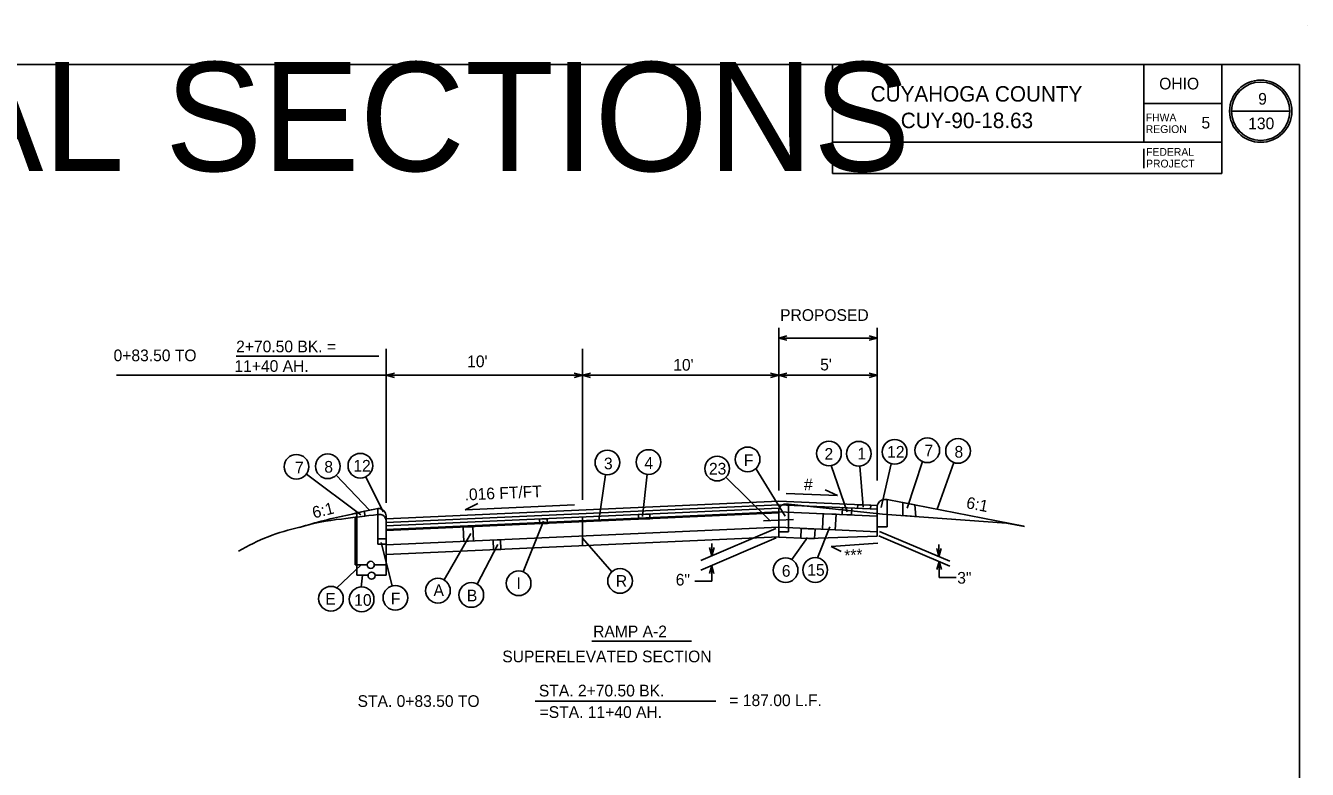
# Model space of a CAD drawing. Extents: x -210 to 558, y -150 to 205.
# Drawn here: x 491.9 to 557.8, y -100.6 to -62.3 of the extents above; entities that cross this region are included whole.
import ezdxf

# ---------------------------------------------------------------- set-up
doc = ezdxf.new("R2010")
doc.units = 0
for name, color, linetype in [('Level 1', 7, 'Continuous'), ('Level 2', 7, 'Continuous'), ('Level 4', 7, 'Continuous'), ('Level 6', 7, 'Continuous'), ('Level 60', 7, 'Continuous'), ('Level 7', 7, 'Continuous')]:
    doc.layers.add(name, color=color, linetype=linetype)

msp = doc.modelspace()

# ---------------------------------------------------------------- linework, layer by layer
at = {"layer": 'Level 1'}
for p, q in [((557.752, -62.346), (557.752, -62.346)), ((557.356, -64.342), (423.408, -64.342)), ((557.356, -148.31), (557.356, -64.342))]:
    msp.add_line(p, q, dxfattribs=at)
at = {"layer": 'Level 2'}
for p, q in [((533.364, -64.342), (533.364, -66.342)), ((549.356, -64.342), (549.356, -66.342)), ((553.356, -64.342), (553.356, -66.342)), ((533.364, -66.342), (533.364, -68.342)), ((549.356, -66.342), (549.356, -68.342)), ((549.356, -66.342), (553.356, -66.342)), ((553.356, -66.342), (553.356, -68.342)), ((556.856, -66.742), (553.856, -66.742)), ((533.364, -68.342), (533.364, -69.942)), ((533.364, -68.342), (553.356, -68.342)), ((553.356, -68.342), (553.356, -69.942)), ((549.356, -68.674), (549.356, -69.674)), ((533.364, -69.942), (553.356, -69.942))]:
    msp.add_line(p, q, dxfattribs=at)
for radius in [1.599, 1.499]:
    msp.add_circle((555.356, -66.743), radius, dxfattribs=at)
at = {"layer": 'Level 4'}
for p, q in [((530.608, -86.23), (530.608, -77.879)), ((535.67, -85.715), (535.67, -77.879)), ((510.451, -86.855), (510.451, -78.954)), ((520.53, -78.954), (520.53, -86.704)), ((530.608, -78.397), (535.67, -78.397)), ((502.745, -79.325), (510.076, -79.325)), ((510.451, -80.312), (496.606, -80.312)), ((510.451, -80.312), (520.53, -80.312)), ((520.53, -80.312), (530.608, -80.312)), ((530.608, -80.312), (535.67, -80.312)), ((535.67, -85.715), (535.67, -82.128)), ((536.388, -84.855), (535.873, -87.099)), ((537.993, -84.748), (537.204, -87.137)), ((539.602, -84.795), (538.751, -87.196)), ((506.351, -85.39), (509.143, -87.482)), ((507.888, -85.443), (509.587, -87.233)), ((509.405, -85.526), (510.293, -87.325)), ((521.717, -85.419), (521.372, -87.775)), ((523.851, -85.397), (523.605, -87.561)), ((530.149, -87.776), (527.895, -85.551)), ((529.439, -85.097), (530.935, -87.548)), ((533.3, -84.952), (534.121, -87.318)), ((534.77, -84.972), (534.939, -87.067)), ((533.622, -86.495), (532.99, -86.191)), ((530.99, -86.377), (533.622, -86.495)), ((514.498, -87.22), (515.163, -86.9)), ((520.123, -86.968), (514.498, -87.22)), ((517.488, -90.408), (518.529, -87.808)), ((530.451, -88.187), (526.615, -89.819)), ((533.227, -88.095), (532.59, -89.689)), ((513.425, -90.826), (514.803, -88.436)), ((522.042, -90.4), (520.53, -88.682)), ((530.482, -88.67), (526.615, -90.316)), ((532.078, -88.638), (531.287, -89.782)), ((535.754, -88.562), (539.398, -90.113)), ((535.784, -88.333), (539.388, -89.867)), ((510.766, -91.128), (510.189, -88.894)), ((515.116, -91.037), (516.189, -88.998)), ((527.169, -89.583), (527.169, -88.954)), ((533.301, -89.101), (535.695, -88.931)), ((533.301, -89.101), (533.815, -89.366)), ((538.834, -89.631), (538.834, -89.002)), ((509.173, -90.05), (507.918, -91.233)), ((527.169, -90.895), (527.169, -90.08)), ((538.844, -90.692), (538.844, -89.877)), ((509.233, -90.576), (509.158, -91.188)), ((539.72, -90.692), (538.844, -90.692)), ((526.293, -90.895), (527.169, -90.895)), ((521.018, -93.977), (526.126, -93.977)), ((518.101, -97.048), (527.371, -97.048))]:
    msp.add_line(p, q, dxfattribs=at)
for points in [[(531.028, -78.513), (530.608, -78.397), (531.028, -78.285)], [(535.25, -78.281), (535.67, -78.397), (535.25, -78.509)], [(510.871, -80.428), (510.451, -80.312), (510.871, -80.2)], [(520.11, -80.196), (520.53, -80.312), (520.11, -80.424)], [(520.95, -80.428), (520.53, -80.312), (520.95, -80.2)], [(530.188, -80.196), (530.608, -80.312), (530.188, -80.424)], [(531.028, -80.428), (530.608, -80.312), (531.028, -80.2)], [(535.25, -80.196), (535.67, -80.312), (535.25, -80.424)], [(527.285, -89.163), (527.169, -89.583), (527.057, -89.163)], [(538.718, -89.211), (538.834, -89.631), (538.946, -89.211)], [(527.053, -90.5), (527.169, -90.08), (527.281, -90.5)], [(538.96, -90.297), (538.844, -89.877), (538.732, -90.297)]]:
    msp.add_lwpolyline(points, dxfattribs=at)
for centre in [(538.234, -84.162), (539.814, -84.197), (521.809, -84.791), (523.923, -84.767), (529.01, -84.631), (533.187, -84.328), (534.719, -84.34), (536.56, -84.245), (505.843, -85.01), (507.451, -84.984), (509.125, -84.957), (527.446, -85.104), (530.96, -90.326), (532.48, -90.314), (513.108, -91.376), (517.252, -90.996), (522.461, -90.876), (507.616, -91.79), (509.191, -91.821), (510.925, -91.742), (514.821, -91.598)]:
    msp.add_circle(centre, 0.634, dxfattribs=at)
at = {"layer": 'Level 6'}
for p, q in [((510.028, -87.461), (510.028, -88.987)), ((510.028, -87.461), (510.182, -87.461)), ((510.451, -88.05), (530.608, -87.145)), ((510.451, -88.29), (530.608, -87.385)), ((530.608, -87.145), (530.608, -88.617)), ((530.882, -86.933), (531.108, -86.933)), ((531.108, -86.933), (535.943, -87.443)), ((531.108, -86.933), (531.108, -88.35)), ((535.943, -87.443), (542.303, -87.905)), ((508.856, -87.608), (508.856, -90.05)), ((510.451, -87.754), (510.451, -90.05)), ((510.451, -89.024), (530.608, -88.119)), ((520.53, -87.597), (520.53, -89.069)), ((542.303, -87.905), (543.221, -88.08)), ((510.451, -89.522), (530.608, -88.617)), ((530.608, -88.35), (531.108, -88.35)), ((510.028, -88.987), (510.451, -88.987)), ((508.856, -90.05), (509.447, -90.05)), ((509.837, -90.05), (510.451, -90.05))]:
    msp.add_line(p, q, dxfattribs=at)
msp.add_circle((509.657, -90.051), 0.183, dxfattribs=at)
for centre, radius, start, end in [((421.754, 616.089), 709.066, 276.998467, 277.151492), ((510.097, -87.809), 0.359, 8.91155, 76.24656), ((530.969, -87.286), 0.363, 103.89297, 186.01636), ((508.305, -98.646), 10.774, 102.28567, 120.31113), ((509.429, -99.722), 12.095, 96.07186, 106.45302)]:
    msp.add_arc(centre, radius, start, end, dxfattribs=at)
at = {"layer": 'Level 60'}
for points in [[(536.98, -87.519), (536.972, -86.849), (537.599, -86.971), (537.645, -87.567)], [(508.948, -87.596), (509.353, -87.545), (509.345, -87.293), (508.93, -87.386)], [(523.414, -87.708), (523.403, -87.468), (523.984, -87.442), (523.994, -87.682)], [(533.513, -88.25), (533.549, -87.454), (532.895, -87.425), (532.859, -88.221)], [(534.351, -87.486), (534.367, -87.131), (533.887, -87.11), (533.871, -87.464)], [(535.328, -87.176), (535.337, -86.99), (534.664, -86.96), (534.655, -87.146)], [(514.437, -88.846), (514.404, -88.113), (514.901, -88.091), (514.934, -88.823)], [(518.333, -87.937), (518.322, -87.696), (518.724, -87.678), (518.735, -87.918)], [(531.742, -88.68), (532.135, -88.699), (532.447, -88.688), (532.478, -88.209), (531.755, -88.178)], [(515.959, -89.274), (515.937, -88.778), (516.315, -88.761), (516.337, -89.257)]]:
    msp.add_lwpolyline(points, close=True, dxfattribs=at)
at = {"layer": 'Level 7'}
for p, q in [((530.607, -86.781), (510.451, -87.686)), ((530.607, -86.781), (535.668, -87.008)), ((536.168, -86.693), (536.008, -86.693)), ((536.168, -86.693), (543.185, -88.059)), ((536.168, -88.099), (536.168, -86.693)), ((508.947, -87.382), (508.947, -90.576)), ((510.028, -87.161), (510.028, -88.716)), ((510.028, -87.161), (510.119, -87.161)), ((510.451, -87.872), (530.607, -86.967)), ((510.451, -88.227), (530.622, -87.321)), ((510.451, -87.524), (510.451, -90.576)), ((535.69, -87.196), (530.607, -86.967)), ((530.607, -87.322), (530.607, -88.627)), ((535.654, -87.549), (530.607, -87.322)), ((535.668, -88.572), (535.668, -87.008)), ((529.818, -87.789), (531.36, -87.727)), ((535.668, -88.347), (530.607, -88.12)), ((535.668, -88.099), (536.168, -88.099)), ((510.028, -88.716), (510.451, -88.716)), ((530.607, -88.627), (532.135, -88.699)), ((532.135, -88.699), (535.668, -88.572)), ((508.947, -90.576), (509.521, -90.576)), ((509.882, -90.576), (510.451, -90.576))]:
    msp.add_line(p, q, dxfattribs=at)
msp.add_circle((509.702, -90.603), 0.183, dxfattribs=at)
for centre, radius, start, end in [((536.048, -87.078), 0.387, 96.02749, 169.67861), ((514.586, -116.401), 29.551, 101.48467, 106.57547), ((513.191, -105.388), 18.499, 99.84483, 104.04247), ((510.052, -87.555), 0.4, 4.50116, 80.36352)]:
    msp.add_arc(centre, radius, start, end, dxfattribs=at)

# ---------------------------------------------------------------- texts
at = {"layer": 'Level 1'}
msp.add_text('RAMP TYPICAL SECTIONS', height=5.6, dxfattribs=at).set_placement((442.087, -69.82))
at = {"layer": 'Level 2'}
for s, height, p in [('OHIO', 0.6, (550.143, -65.626)), ('CUYAHOGA COUNTY', 0.795, (535.329, -66.25)), ('9', 0.6, (555.228, -66.407)), ('CUY-90-18.63', 0.795, (536.874, -67.614)), ('FHWA', 0.4, (549.452, -67.265)), ('5', 0.6, (552.314, -67.634)), ('130', 0.6, (554.714, -67.671)), ('REGION', 0.4, (549.452, -67.865)), ('FEDERAL', 0.4, (549.469, -69.034)), ('PROJECT', 0.4, (549.469, -69.634))]:
    msp.add_text(s, height=height, dxfattribs=at).set_placement(p)
at = {"layer": 'Level 4'}
for s, p in [('PROPOSED', (530.678, -77.517)), ('2+70.50 BK. =', (502.746, -79.13)), ('0+83.50 TO', (496.452, -79.588)), ('11+40 AH.', (502.659, -80.134)), ("10'", (514.608, -79.894)), ("10'", (525.191, -80.074)), ("5'", (532.736, -80.06)), ('2', (532.958, -84.648)), ('1', (534.644, -84.636)), ('12', (536.176, -84.541)), ('7', (538.088, -84.482)), ('8', (539.632, -84.541)), ('7', (505.77, -85.35)), ('8', (507.274, -85.311)), ('12', (508.764, -85.259)), ('3', (521.633, -85.141)), ('4', (523.711, -85.117)), ('23', (527.024, -85.409)), ('F', (528.813, -84.969)), ('#', (531.903, -86.222)), ('6', (530.767, -90.658)), ('15', (532.073, -90.61)), ('I', (517.143, -91.285)), ('R', (522.245, -91.176)), ('6"', (525.317, -91.112)), ('3"', (539.774, -91.016)), ('A', (512.882, -91.651)), ('B', (514.594, -91.926)), ('E', (507.322, -92.096)), ('10', (508.809, -92.153)), ('F', (510.689, -92.084)), ('RAMP A-2', (521.077, -93.769)), ('SUPERELEVATED SECTION', (516.412, -95.056)), ('STA. 0+83.50 TO', (508.981, -97.348)), ('STA. 2+70.50 BK. ', (518.291, -96.809)), ('= 187.00 L.F.', (528.073, -97.308)), ('=STA. 11+40 AH.', (518.329, -97.912))]:
    msp.add_text(s, height=0.6, dxfattribs=at).set_placement(p)
for s, rotation, p in [('.016 FT/FT', 2.57074, (514.489, -86.743)), ('6:1', 13.91866, (506.738, -87.669)), ('6:1', 348.97963, (540.202, -87.13)), ('***', 4.07739, (534.002, -89.875))]:
    msp.add_text(s, height=0.6, rotation=rotation, dxfattribs=at).set_placement(p)

doc.saveas('drawing.dxf')
